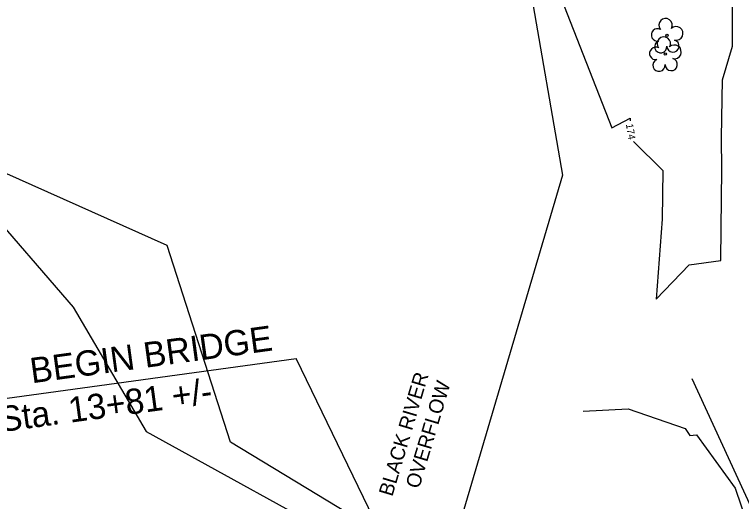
# Model space of a CAD drawing. Extents: x 2086416 to 2115205, y 575507 to 632762.
# Drawn here: x 2111355.3 to 2111556.7, y 581750.1 to 581885 of the extents above; entities that cross this region are included whole.
import ezdxf

# ---------------------------------------------------------------- set-up
doc = ezdxf.new("R2010")
doc.units = 0
for name, color, linetype in [('DTM Contours Minor', 7, 'Continuous'), ('DTM Contours Minor Text', 7, 'Continuous'), ('Exist Hydro Stream or Body of Water', 7, 'Continuous'), ('Exist Hydro Stream or Body of Water Text', 7, 'Continuous'), ('Exist Vegetation Tree CELL', 7, 'Continuous'), ('Exist Vegetation Woods Line', 7, 'Continuous'), ('Prop Horizontal Alignment Station Label', 7, 'Continuous')]:
    doc.layers.add(name, color=color, linetype=linetype)

# ---------------------------------------------------------------- blocks, each defined once
blk = doc.blocks.new('EXIST VEGETATION TREE')
at = {"layer": 'Exist Vegetation Tree CELL'}
blk.add_line((0, 0), (0, 0), dxfattribs=at)
blk.add_circle((0, 0), 0.00652, dxfattribs=at)
for centre, radius, start, end in [((-0.0077, 0.0575), 0.0371, 330.1651, 219.7134), ((0.051, 0.0118), 0.038, 257.1011, 134.1999), ((-0.0521, 0.0031), 0.0345, 62.6636, 279.3457), ((-0.0341, -0.0624), 0.0338, 111.5671, 6.231), ((0.0335, -0.058), 0.034, 181.2822, 74.56)]:
    blk.add_arc(centre, radius, start, end, dxfattribs=at)

msp = doc.modelspace()

# ---------------------------------------------------------------- linework, layer by layer
at = {"layer": 'DTM Contours Minor'}
for points in [[(2111445.49, 582017.55), (2111461.23, 582000.08), (2111467.35, 581984.28), (2111472.77, 581982.89), (2111473.43, 581977.35), (2111483.32, 581966.53), (2111492.15, 581959.39), (2111498.82, 581956.92), (2111498.73, 581950.3), (2111494.14, 581927.18), (2111493.97, 581925.27), (2111493.95, 581923.58), (2111494.25, 581921.56), (2111520.77, 581853.63), (2111525.86, 581856.27), (2111525.9, 581855.52)], [(2111526.82, 581849.8), (2111534.93, 581841.74), (2111534.78, 581828.33), (2111533.09, 581806.08), (2111542.23, 581815.68), (2111551.05, 581816.86), (2111551.14, 581825.76), (2111551.32, 581841.92), (2111551.15, 581850.91), (2111551.49, 581866.87), (2111554.23, 581876.21), (2111554.28, 581889.21), (2111554.4, 581901.08), (2111554.13, 581914.16), (2111554.24, 581926.09), (2111555.12, 581938.87), (2111555.14, 581947.12)], [(2111512.86, 581775.08), (2111525.32, 581775.7), (2111541.08, 581770.28), (2111542.43, 581768.36), (2111544.24, 581768.53), (2111554.95, 581753.72), (2111558.4, 581743.64), (2111555.04, 581736.97), (2111563.15, 581735.16)]]:
    msp.add_lwpolyline(points, dxfattribs=at)
at = {"layer": 'Exist Hydro Stream or Body of Water'}
for points in [[(2111463, 581737.48), (2111415.11, 581766.53), (2111397.64, 581820.96), (2111352.3, 581841.23), (2111333.83, 581869.49), (2111330, 581879.12), (2111337.82, 581902), (2111329.78, 581919.05), (2111313.88, 581938.09), (2111294.11, 581978.61), (2111295.93, 582000.43), (2111293.88, 582015.55), (2111285.78, 582045.07), (2111284.37, 582067.54), (2111288.67, 582094.58), (2111287.89, 582112.99), (2111281.07, 582150.07), (2111274.06, 582190.6)], [(2111453.09, 582094.1), (2111443.96, 582082.97), (2111447.94, 582071.29), (2111430.65, 582047.36), (2111437.21, 582014.64), (2111436.6, 581990.7), (2111456.37, 581961.91), (2111482.37, 581945.66), (2111482.01, 581910.08), (2111498.18, 581892.27), (2111507.18, 581840.49), (2111478.63, 581743.8)]]:
    msp.add_lwpolyline(points, dxfattribs=at)
at = {"layer": 'Exist Vegetation Woods Line'}
for points in [[(2111262.29, 582184.02), (2111265.31, 582083.43), (2111279.98, 581987.09), (2111311.55, 581918.74), (2111324.25, 581867.33), (2111346.25, 581833.12), (2111371.51, 581803.94), (2111391.8, 581769.41), (2111452.1, 581736.22)], [(2111543, 581784.1), (2111565.77, 581734.52), (2111587.19, 581707.45), (2111708.99, 581713.78), (2111811.99, 581727.73), (2111909.41, 581740.4), (2112007.41, 581746.55), (2112041.96, 581749.79), (2112042.22, 581740.22)]]:
    msp.add_lwpolyline(points, dxfattribs=at)
at = {"layer": 'Prop Horizontal Alignment Station Label'}
for p in [(2111302.64, 581771.83), (2111502.04, 581648.05)]:
    msp.add_line(p, (2111433.3, 581789.66), dxfattribs=at)

# ---------------------------------------------------------------- block references
at = {"layer": 'Exist Vegetation Tree CELL', "xscale": 50, "yscale": 50}
for p in [(2111536.07, 581879.2), (2111535.59, 581874.05)]:
    msp.add_blockref('EXIST VEGETATION TREE', p, dxfattribs=at)

# ---------------------------------------------------------------- texts
at = {"layer": 'DTM Contours Minor Text'}
msp.add_text('174', height=2, rotation=279.1936, dxfattribs=at).set_placement((2111524.7, 581854.61))
at = {"layer": 'Exist Hydro Stream or Body of Water Text'}
for s, p in [('BLACK RIVER', (2111459.97, 581751.26)), ('OVERFLOW', (2111467.4, 581753.4))]:
    msp.add_text(s, height=4, rotation=73.3933, dxfattribs=at).set_placement(p)
at = {"layer": 'Prop Horizontal Alignment Station Label'}
for s, p in [('BEGIN BRIDGE', (2111360.1, 581782.8)), ('-L- POT Sta. 13+81 +/-  ', (2111316.09, 581764.43))]:
    msp.add_text(s, height=7, rotation=7.771, dxfattribs=at).set_placement(p)

doc.saveas('drawing.dxf')
